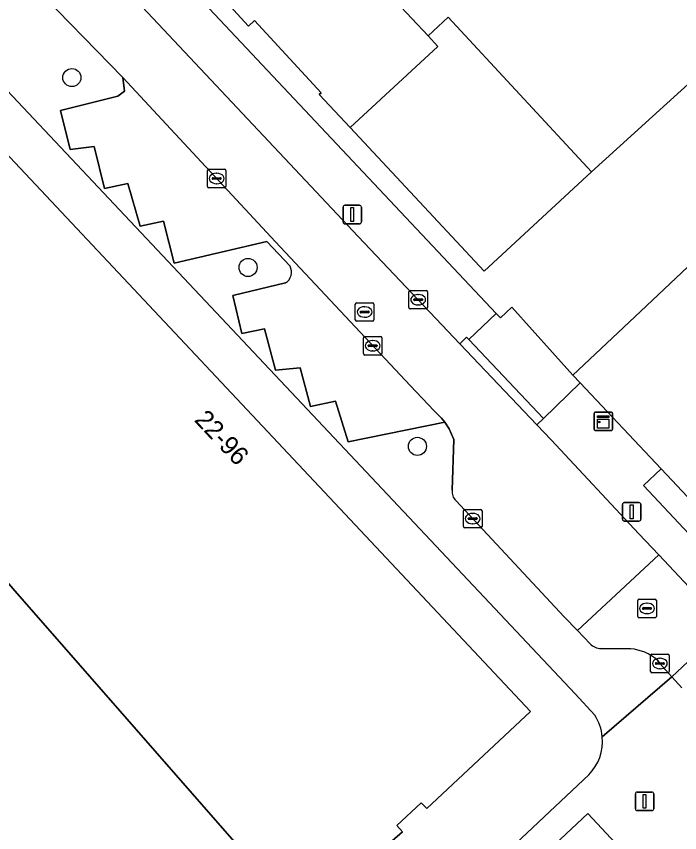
# Model space of a CAD drawing. Extents: x 162344 to 162869, y 381217 to 381818.
# Drawn here: x 162722.83 to 162758.59, y 381421.83 to 381465.85 of the extents above; entities that cross this region are included whole.
import ezdxf

# ---------------------------------------------------------------- set-up
doc = ezdxf.new("R2010")
doc.units = 0
for name, color, linetype in [('IMGEO_Boom', 7, 'Continuous'), ('IMGEO_Erf', 7, 'Continuous'), ('IMGEO_Groenvoorziening', 7, 'Continuous'), ('IMGEO_Kast', 7, 'Continuous'), ('IMGEO_Kolk', 7, 'Continuous'), ('IMGEO_Lichtmast', 7, 'Continuous'), ('IMGEO_Pand', 7, 'Continuous'), ('IMGEO_Pand_nummerreeks', 7, 'Continuous'), ('IMGEO_Pand_overbouw', 7, 'Continuous'), ('IMGEO_Parkeervlak_open', 7, 'Continuous'), ('IMGEO_Rijbaan_lokaal_gesloten', 7, 'Continuous'), ('IMGEO_Rijbaan_lokaal_open', 7, 'Continuous'), ('IMGEO_Rioolput', 7, 'Continuous'), ('IMGEO_Voetpad_open', 7, 'Continuous')]:
    doc.layers.add(name, color=color, linetype=linetype)

msp = doc.modelspace()

# ---------------------------------------------------------------- linework, layer by layer
at = {"layer": 'IMGEO_Boom'}
for centre in [(162725.827, 381462.544), (162735.326, 381452.306), (162744.456, 381442.659)]:
    msp.add_circle(centre, 0.489, dxfattribs=at)
at = {"layer": 'IMGEO_Erf'}
for points in [[(162776.168, 381478.463), (162768.577, 381485.812), (162766.682, 381483.846), (162766.126, 381484.385), (162763.326, 381487.099), (162760.614, 381484.574), (162742.401, 381467.62), (162745.028, 381464.791), (162745.55, 381464.229), (162740.832, 381459.846), (162748.057, 381452.099), (162753.839, 381457.469), (162770.656, 381472.745)], [(162707.761, 381447.96), (162713.091, 381453.729), (162713.48, 381453.373), (162715.221, 381455.005), (162713.929, 381456.387), (162719.413, 381461.511), (162750.55, 381428.359), (162744.956, 381423.125), (162744.66, 381423.433), (162743.338, 381422.213), (162743.645, 381421.881), (162738.243, 381417.16), (162722.757, 381434.865), (162721.886, 381435.861), (162721.396, 381435.328)]]:
    msp.add_lwpolyline(points, close=True, dxfattribs=at)
for points in [[(162754.013, 381428.168), (162752.967, 381429.308), (162720.009, 381464.312)], [(162688.76, 381363.938), (162688.853, 381363.831), (162718.753, 381392.02), (162718.479, 381392.369), (162730.05, 381403.284), (162730.365, 381402.935), (162734.043, 381406.444), (162753.688, 381424.95)]]:
    msp.add_lwpolyline(points, dxfattribs=at)
for centre, radius, start, end in [((162751.844, 381426.758), 2.587, 5.2253, 33.0153), ((162751.847, 381426.762), 2.584, 315.4502, 5.1428)]:
    msp.add_arc(centre, radius, start, end, dxfattribs=at)
at = {"layer": 'IMGEO_Groenvoorziening'}
msp.add_lwpolyline([(162756.875, 381419.391), (162753.639, 381422.863), (162748.623, 381418.154), (162750.4, 381416.271)], dxfattribs=at)
at = {"layer": 'IMGEO_Kast'}
for p, q in [((162753.976, 381443.584), (162753.976, 381444.425)), ((162753.976, 381444.425), (162753.976, 381443.584)), ((162754.051, 381444.509), (162754.892, 381444.509)), ((162754.892, 381444.509), (162754.051, 381444.509)), ((162754.976, 381444.434), (162754.976, 381443.593)), ((162754.976, 381443.593), (162754.976, 381444.434)), ((162754.901, 381443.509), (162754.06, 381443.509)), ((162754.06, 381443.509), (162754.901, 381443.509))]:
    msp.add_line(p, q, dxfattribs=at)
for points in [[(162754.171, 381444.299), (162754.771, 381444.299), (162754.771, 381444.214), (162754.171, 381444.214), (162754.171, 381444.299)], [(162754.171, 381444.124), (162754.771, 381444.124), (162754.771, 381443.635), (162754.171, 381443.635), (162754.171, 381444.124)]]:
    msp.add_lwpolyline(points, dxfattribs=at)
msp.add_circle((162754.255, 381443.973), 0.0377, dxfattribs=at)
for centre, start, end in [((162754.054, 381444.431), 92.4484, 184.2845), ((162754.054, 381444.431), 92.4484, 184.2845), ((162754.898, 381444.431), 2.4484, 94.2845), ((162754.898, 381444.431), 2.4484, 94.2845), ((162754.054, 381443.587), 182.4484, 274.2845), ((162754.054, 381443.587), 182.4484, 274.2845), ((162754.898, 381443.587), 272.4484, 4.2845), ((162754.898, 381443.587), 272.4484, 4.2845)]:
    msp.add_arc(centre, 0.0779, start, end, dxfattribs=at)
at = {"layer": 'IMGEO_Kolk'}
for p, q in [((162733.134, 381456.676), (162733.134, 381457.528)), ((162733.209, 381457.602), (162734.061, 381457.602)), ((162733.622, 381457.382), (162733.647, 381457.382)), ((162734.135, 381457.528), (162734.135, 381456.676)), ((162733.393, 381457.096), (162733.393, 381457.108)), ((162733.831, 381457.059), (162733.433, 381457.059)), ((162733.436, 381457.145), (162733.834, 381457.145)), ((162733.877, 381457.108), (162733.877, 381457.096)), ((162734.061, 381456.602), (162733.209, 381456.602)), ((162733.645, 381456.822), (162733.62, 381456.822)), ((162743.995, 381450.141), (162743.995, 381450.993)), ((162744.07, 381451.067), (162744.922, 381451.067)), ((162744.483, 381450.847), (162744.508, 381450.847)), ((162744.996, 381450.993), (162744.996, 381450.141)), ((162744.254, 381450.561), (162744.254, 381450.573)), ((162744.692, 381450.524), (162744.294, 381450.524)), ((162744.297, 381450.61), (162744.695, 381450.61)), ((162744.738, 381450.573), (162744.738, 381450.561)), ((162744.922, 381450.067), (162744.07, 381450.067)), ((162744.506, 381450.287), (162744.481, 381450.287)), ((162741.617, 381448.584), (162742.469, 381448.584)), ((162741.542, 381447.658), (162741.542, 381448.51)), ((162741.844, 381448.127), (162742.242, 381448.127)), ((162742.03, 381448.364), (162742.055, 381448.364)), ((162742.543, 381448.51), (162742.543, 381447.658)), ((162741.801, 381448.078), (162741.801, 381448.09)), ((162742.239, 381448.041), (162741.841, 381448.041)), ((162742.053, 381447.804), (162742.028, 381447.804)), ((162742.285, 381448.09), (162742.285, 381448.078)), ((162742.469, 381447.584), (162741.617, 381447.584)), ((162746.936, 381438.336), (162746.936, 381439.188)), ((162747.011, 381439.262), (162747.863, 381439.262)), ((162747.424, 381439.042), (162747.449, 381439.042)), ((162747.937, 381439.188), (162747.937, 381438.336)), ((162747.195, 381438.756), (162747.195, 381438.768)), ((162747.633, 381438.719), (162747.235, 381438.719)), ((162747.238, 381438.805), (162747.636, 381438.805)), ((162747.447, 381438.482), (162747.422, 381438.482)), ((162747.679, 381438.768), (162747.679, 381438.756)), ((162747.863, 381438.262), (162747.011, 381438.262)), ((162757.099, 381431.45), (162757.951, 381431.45)), ((162757.024, 381430.524), (162757.024, 381431.376)), ((162757.283, 381430.944), (162757.283, 381430.956)), ((162757.326, 381430.993), (162757.724, 381430.993)), ((162757.512, 381431.23), (162757.537, 381431.23)), ((162757.767, 381430.956), (162757.767, 381430.944)), ((162758.025, 381431.376), (162758.025, 381430.524)), ((162757.721, 381430.907), (162757.323, 381430.907)), ((162757.535, 381430.67), (162757.51, 381430.67)), ((162757.951, 381430.45), (162757.099, 381430.45))]:
    msp.add_line(p, q, dxfattribs=at)
for points in [[(162733.134, 381456.676), (162733.134, 381457.528)], [(162733.209, 381457.602), (162734.061, 381457.602)], [(162734.135, 381457.528), (162734.135, 381456.676)], [(162734.061, 381456.602), (162733.209, 381456.602)], [(162743.995, 381450.141), (162743.995, 381450.993)], [(162744.07, 381451.067), (162744.922, 381451.067)], [(162744.996, 381450.993), (162744.996, 381450.141)], [(162744.922, 381450.067), (162744.07, 381450.067)], [(162741.617, 381448.584), (162742.469, 381448.584)], [(162741.542, 381447.658), (162741.542, 381448.51)], [(162742.543, 381448.51), (162742.543, 381447.658)], [(162742.469, 381447.584), (162741.617, 381447.584)], [(162746.936, 381438.336), (162746.936, 381439.188)], [(162747.011, 381439.262), (162747.863, 381439.262)], [(162747.937, 381439.188), (162747.937, 381438.336)], [(162747.863, 381438.262), (162747.011, 381438.262)], [(162757.099, 381431.45), (162757.951, 381431.45)], [(162757.024, 381430.524), (162757.024, 381431.376)], [(162758.025, 381431.376), (162758.025, 381430.524)], [(162757.951, 381430.45), (162757.099, 381430.45)]]:
    msp.add_lwpolyline(points, dxfattribs=at)
for centre, radius, start, end in [((162733.211, 381457.526), 0.0765, 91.552, 178.448), ((162733.211, 381457.526), 0.0765, 91.552, 178.448), ((162734.059, 381457.526), 0.0765, 1.552, 88.448), ((162734.059, 381457.526), 0.0765, 1.552, 88.448), ((162733.433, 381457.105), 0.0403, 85.8775, 175.7526), ((162733.43, 381457.095), 0.0366, 178.938, 274.7102), ((162733.834, 381457.102), 0.043, 264.8664, 352.4533), ((162733.838, 381457.107), 0.0386, 1.7309, 96.639), ((162733.211, 381456.678), 0.0765, 181.552, 268.448), ((162733.211, 381456.678), 0.0765, 181.552, 268.448), ((162734.059, 381456.678), 0.0765, 271.552, 358.448), ((162734.059, 381456.678), 0.0765, 271.552, 358.448), ((162744.072, 381450.991), 0.0765, 91.552, 178.448), ((162744.072, 381450.991), 0.0765, 91.552, 178.448), ((162744.92, 381450.991), 0.0765, 1.552, 88.448), ((162744.92, 381450.991), 0.0765, 1.552, 88.448), ((162744.294, 381450.57), 0.0403, 85.8775, 175.7526), ((162744.291, 381450.56), 0.0366, 178.938, 274.7102), ((162744.695, 381450.567), 0.043, 264.8664, 352.4533), ((162744.699, 381450.572), 0.0386, 1.7309, 96.639), ((162744.072, 381450.143), 0.0765, 181.552, 268.448), ((162744.072, 381450.143), 0.0765, 181.552, 268.448), ((162744.92, 381450.143), 0.0765, 271.552, 358.448), ((162744.92, 381450.143), 0.0765, 271.552, 358.448), ((162741.619, 381448.508), 0.0765, 91.552, 178.448), ((162741.619, 381448.508), 0.0765, 91.552, 178.448), ((162742.467, 381448.508), 0.0765, 1.552, 88.448), ((162742.467, 381448.508), 0.0765, 1.552, 88.448), ((162741.841, 381448.087), 0.0403, 85.8775, 175.7526), ((162742.246, 381448.089), 0.0386, 1.7309, 96.639), ((162741.838, 381448.077), 0.0366, 178.938, 274.7102), ((162742.242, 381448.084), 0.043, 264.8664, 352.4533), ((162741.619, 381447.66), 0.0765, 181.552, 268.448), ((162741.619, 381447.66), 0.0765, 181.552, 268.448), ((162742.467, 381447.66), 0.0765, 271.552, 358.448), ((162742.467, 381447.66), 0.0765, 271.552, 358.448), ((162747.013, 381439.186), 0.0765, 91.552, 178.448), ((162747.013, 381439.186), 0.0765, 91.552, 178.448), ((162747.861, 381439.186), 0.0765, 1.552, 88.448), ((162747.861, 381439.186), 0.0765, 1.552, 88.448), ((162747.235, 381438.765), 0.0403, 85.8775, 175.7526), ((162747.232, 381438.755), 0.0366, 178.938, 274.7102), ((162747.636, 381438.762), 0.043, 264.8664, 352.4533), ((162747.64, 381438.767), 0.0386, 1.7309, 96.639), ((162747.013, 381438.338), 0.0765, 181.552, 268.448), ((162747.013, 381438.338), 0.0765, 181.552, 268.448), ((162747.861, 381438.338), 0.0765, 271.552, 358.448), ((162747.861, 381438.338), 0.0765, 271.552, 358.448), ((162757.101, 381431.374), 0.0765, 91.552, 178.448), ((162757.101, 381431.374), 0.0765, 91.552, 178.448), ((162757.949, 381431.374), 0.0765, 1.552, 88.448), ((162757.949, 381431.374), 0.0765, 1.552, 88.448), ((162757.323, 381430.953), 0.0403, 85.8775, 175.7526), ((162757.728, 381430.955), 0.0386, 1.7309, 96.639), ((162757.101, 381430.526), 0.0765, 181.552, 268.448), ((162757.101, 381430.526), 0.0765, 181.552, 268.448), ((162757.32, 381430.943), 0.0366, 178.938, 274.7102), ((162757.724, 381430.95), 0.043, 264.8664, 352.4533), ((162757.949, 381430.526), 0.0765, 271.552, 358.448), ((162757.949, 381430.526), 0.0765, 271.552, 358.448)]:
    msp.add_arc(centre, radius, start, end, dxfattribs=at)
for centre, major_axis, ratio, start_param, end_param in [((162733.621, 381457.102), (-0.387, 0.002), 0.722429, 4.712389, 7.853982), ((162733.646, 381457.102), (-0.39, 0.002), 0.717154, 1.570796, 4.712389), ((162744.482, 381450.567), (-0.387, 0.002), 0.722429, 4.712389, 7.853982), ((162744.507, 381450.567), (-0.39, 0.002), 0.717154, 1.570796, 4.712389), ((162742.029, 381448.084), (-0.387, 0.002), 0.722429, 4.712389, 7.853982), ((162742.054, 381448.084), (-0.39, 0.002), 0.717154, 1.570796, 4.712389), ((162747.423, 381438.762), (-0.387, 0.002), 0.722429, 4.712389, 7.853982), ((162747.448, 381438.762), (-0.39, 0.002), 0.717154, 1.570796, 4.712389), ((162757.511, 381430.95), (-0.387, 0.002), 0.722429, 4.712389, 7.853982), ((162757.536, 381430.95), (-0.39, 0.002), 0.717154, 1.570796, 4.712389)]:
    msp.add_ellipse(centre, major_axis=major_axis, ratio=ratio, start_param=start_param, end_param=end_param, dxfattribs=at)
at = {"layer": 'IMGEO_Lichtmast'}
for p, q in [((162740.543, 381455.657), (162741.333, 381455.657)), ((162741.333, 381455.657), (162740.543, 381455.657)), ((162740.443, 381454.757), (162740.443, 381455.557)), ((162740.443, 381455.557), (162740.443, 381454.757)), ((162741.433, 381455.557), (162741.433, 381454.757)), ((162741.433, 381454.757), (162741.433, 381455.557)), ((162741.333, 381454.657), (162740.543, 381454.657)), ((162740.543, 381454.657), (162741.333, 381454.657)), ((162755.508, 381438.727), (162755.508, 381439.527)), ((162755.508, 381439.527), (162755.508, 381438.727)), ((162755.608, 381439.627), (162756.398, 381439.627)), ((162756.398, 381439.627), (162755.608, 381439.627)), ((162756.498, 381439.527), (162756.498, 381438.727)), ((162756.498, 381438.727), (162756.498, 381439.527)), ((162756.398, 381438.627), (162755.608, 381438.627)), ((162755.608, 381438.627), (162756.398, 381438.627)), ((162756.205, 381423.118), (162756.205, 381423.918)), ((162756.205, 381423.918), (162756.205, 381423.118)), ((162756.305, 381424.018), (162757.095, 381424.018)), ((162757.095, 381424.018), (162756.305, 381424.018)), ((162757.195, 381423.918), (162757.195, 381423.118)), ((162757.195, 381423.118), (162757.195, 381423.918)), ((162757.095, 381423.018), (162756.305, 381423.018)), ((162756.305, 381423.018), (162757.095, 381423.018))]:
    msp.add_line(p, q, dxfattribs=at)
for points in [[(162740.863, 381455.532), (162741.013, 381455.532), (162741.013, 381454.782), (162740.863, 381454.782), (162740.863, 381455.532)], [(162755.928, 381439.502), (162756.078, 381439.502), (162756.078, 381438.752), (162755.928, 381438.752), (162755.928, 381439.502)], [(162756.625, 381423.893), (162756.775, 381423.893), (162756.775, 381423.143), (162756.625, 381423.143), (162756.625, 381423.893)]]:
    msp.add_lwpolyline(points, dxfattribs=at)
for centre, start, end in [((162740.543, 381455.557), 90, 180), ((162740.543, 381455.557), 90, 180), ((162741.333, 381455.557), 0, 90), ((162741.333, 381455.557), 360, 90), ((162740.543, 381454.757), 180, 270), ((162740.543, 381454.757), 180, 270), ((162741.333, 381454.757), 270, 0), ((162741.333, 381454.757), 270, 0), ((162755.608, 381439.527), 90, 180), ((162755.608, 381439.527), 90, 180), ((162756.398, 381439.527), 0, 90), ((162756.398, 381439.527), 360, 90), ((162755.608, 381438.727), 180, 270), ((162755.608, 381438.727), 180, 270), ((162756.398, 381438.727), 270, 0), ((162756.398, 381438.727), 270, 0), ((162756.305, 381423.918), 90, 180), ((162756.305, 381423.918), 90, 180), ((162757.095, 381423.918), 0, 90), ((162757.095, 381423.918), 360, 90), ((162756.305, 381423.118), 180, 270), ((162756.305, 381423.118), 180, 270), ((162757.095, 381423.118), 270, 0), ((162757.095, 381423.118), 270, 0)]:
    msp.add_arc(centre, 0.1, start, end, dxfattribs=at)
at = {"layer": 'IMGEO_Pand'}
for points in [[(162766.126, 381484.385), (162766.682, 381483.846), (162768.577, 381485.812), (162768.536, 381485.851), (162758.304, 381495.766), (162752.699, 381489.967), (162754.084, 381488.603), (162751.474, 381486.208), (162750.603, 381487.146), (162742.067, 381479.233), (162741.819, 381479.502), (162731.299, 381469.745), (162735.357, 381465.316), (162735.681, 381465.613), (162739.259, 381461.73), (162739.157, 381461.634), (162740.832, 381459.846), (162745.55, 381464.229), (162745.028, 381464.791), (162742.401, 381467.62), (162760.614, 381484.574), (162763.326, 381487.099)], [(162752.835, 381446.506), (162753.232, 381446.083), (162757.597, 381441.444), (162762.133, 381436.621), (162793.032, 381465.683), (162788.482, 381470.52), (162783.734, 381475.568), (162780.092, 381472.143), (162777.709, 381469.901), (162778.4, 381469.165), (162775.312, 381466.261), (162774.596, 381467.023), (162762.149, 381455.316), (162762.834, 381454.587), (162759.69, 381451.63), (162759.03, 381452.332), (162756.477, 381449.931)], [(162713.929, 381456.387), (162715.221, 381455.005), (162713.48, 381453.373), (162713.091, 381453.729), (162707.761, 381447.96), (162721.396, 381435.328), (162721.886, 381435.861), (162722.757, 381434.865), (162738.243, 381417.16), (162743.645, 381421.881), (162743.338, 381422.213), (162744.66, 381423.433), (162744.956, 381423.125), (162750.55, 381428.359), (162719.413, 381461.511)]]:
    msp.add_lwpolyline(points, close=True, dxfattribs=at)
at = {"layer": 'IMGEO_Pand_overbouw'}
msp.add_lwpolyline([(162746.112, 381465.798), (162745.028, 381464.791), (162745.55, 381464.229), (162740.832, 381459.846), (162748.057, 381452.099), (162753.839, 381457.469)], close=True, dxfattribs=at)
at = {"layer": 'IMGEO_Parkeervlak_open'}
msp.add_lwpolyline([(162737.337, 381451.473), (162734.498, 381450.795), (162734.993, 381448.741), (162736.21, 381448.99), (162736.808, 381446.772), (162738.127, 381446.895), (162738.686, 381444.816), (162740.043, 381445.104), (162740.729, 381442.9), (162745.941, 381443.968), (162745.755, 381444.185), (162745.358, 381444.567), (162744.056, 381445.934), (162736.812, 381453.682), (162728.576, 381462.553), (162728.666, 381461.803), (162728.3, 381461.547), (162725.207, 381460.778), (162725.728, 381458.662), (162727.034, 381458.822), (162727.594, 381456.566), (162728.837, 381456.828), (162729.511, 381454.534), (162730.766, 381454.796), (162731.339, 381452.54), (162736.333, 381453.714), (162737.586, 381452.376)], dxfattribs=at)
msp.add_arc((162736.998, 381452.052), 0.671, 300.3536, 28.8143, dxfattribs=at)
at = {"layer": 'IMGEO_Rijbaan_lokaal_gesloten'}
for points in [[(162751.665, 381443.002), (162750.893, 381443.816), (162746.741, 381448.196), (162741.261, 381453.977), (162726.224, 381469.983), (162725.57, 381470.679), (162722.909, 381468.374), (162723.627, 381467.636), (162728.576, 381462.553), (162736.812, 381453.682), (162744.056, 381445.934), (162745.358, 381444.567), (162745.755, 381444.185), (162745.941, 381443.968), (162746.172, 381443.603), (162746.409, 381443.032), (162746.335, 381440.302)], [(162746.532, 381439.731), (162752.372, 381433.475), (162753.083, 381432.727), (162757.473, 381436.804), (162756.391, 381437.951), (162751.665, 381443.002)]]:
    msp.add_lwpolyline(points, dxfattribs=at)
msp.add_arc((162746.951, 381440.195), 0.625, 170.1446, 227.9252, dxfattribs=at)
at = {"layer": 'IMGEO_Rijbaan_lokaal_open'}
for points in [[(162757.473, 381436.804), (162753.083, 381432.727), (162753.768, 381432.007)], [(162757.39, 381431.122), (162757.525, 381430.95), (162758.176, 381430.227), (162761.099, 381432.973), (162760.457, 381433.637), (162757.473, 381436.804)], [(162761.657, 381432.397), (162761.099, 381432.973), (162758.176, 381430.227), (162758.705, 381429.64)], [(162754.359, 381431.752), (162755.949, 381431.738)]]:
    msp.add_lwpolyline(points, dxfattribs=at)
for centre, radius, start, end in [((162754.388, 381432.631), 0.88, 225.2051, 268.1172), ((162755.801, 381429.398), 2.344, 47.3292, 86.3792)]:
    msp.add_arc(centre, radius, start, end, dxfattribs=at)
at = {"layer": 'IMGEO_Rioolput'}
for p, q in [((162741.107, 381449.478), (162741.107, 381450.33)), ((162741.182, 381450.404), (162742.034, 381450.404)), ((162742.108, 381450.33), (162742.108, 381449.478)), ((162741.366, 381449.898), (162741.366, 381449.91)), ((162741.409, 381449.947), (162741.807, 381449.947)), ((162741.595, 381450.184), (162741.62, 381450.184)), ((162741.85, 381449.91), (162741.85, 381449.898)), ((162741.804, 381449.861), (162741.406, 381449.861)), ((162741.618, 381449.624), (162741.593, 381449.624)), ((162742.034, 381449.404), (162741.182, 381449.404)), ((162756.335, 381433.493), (162756.335, 381434.345)), ((162756.41, 381434.419), (162757.262, 381434.419)), ((162756.823, 381434.199), (162756.848, 381434.199)), ((162757.336, 381434.345), (162757.336, 381433.493)), ((162756.594, 381433.913), (162756.594, 381433.925)), ((162757.032, 381433.876), (162756.634, 381433.876)), ((162756.637, 381433.962), (162757.035, 381433.962)), ((162756.846, 381433.639), (162756.821, 381433.639)), ((162757.078, 381433.925), (162757.078, 381433.913)), ((162757.262, 381433.419), (162756.41, 381433.419))]:
    msp.add_line(p, q, dxfattribs=at)
for points in [[(162741.107, 381449.478), (162741.107, 381450.33)], [(162741.182, 381450.404), (162742.034, 381450.404)], [(162742.108, 381450.33), (162742.108, 381449.478)], [(162742.034, 381449.404), (162741.182, 381449.404)], [(162756.335, 381433.493), (162756.335, 381434.345)], [(162756.41, 381434.419), (162757.262, 381434.419)], [(162757.336, 381434.345), (162757.336, 381433.493)], [(162757.262, 381433.419), (162756.41, 381433.419)]]:
    msp.add_lwpolyline(points, dxfattribs=at)
for centre, radius, start, end in [((162741.184, 381450.328), 0.0765, 91.552, 178.448), ((162741.184, 381450.328), 0.0765, 91.552, 178.448), ((162742.032, 381450.328), 0.0765, 1.552, 88.448), ((162742.032, 381450.328), 0.0765, 1.552, 88.448), ((162741.406, 381449.907), 0.0403, 85.8775, 175.7526), ((162741.403, 381449.897), 0.0366, 178.938, 274.7102), ((162741.807, 381449.904), 0.043, 264.8664, 352.4533), ((162741.811, 381449.909), 0.0386, 1.7309, 96.639), ((162741.184, 381449.48), 0.0765, 181.552, 268.448), ((162741.184, 381449.48), 0.0765, 181.552, 268.448), ((162742.032, 381449.48), 0.0765, 271.552, 358.448), ((162742.032, 381449.48), 0.0765, 271.552, 358.448), ((162756.412, 381434.343), 0.0765, 91.552, 178.448), ((162756.412, 381434.343), 0.0765, 91.552, 178.448), ((162757.26, 381434.343), 0.0765, 1.552, 88.448), ((162757.26, 381434.343), 0.0765, 1.552, 88.448), ((162756.634, 381433.922), 0.0403, 85.8775, 175.7526), ((162756.631, 381433.912), 0.0366, 178.938, 274.7102), ((162757.035, 381433.919), 0.043, 264.8664, 352.4533), ((162757.039, 381433.924), 0.0386, 1.7309, 96.639), ((162756.412, 381433.495), 0.0765, 181.552, 268.448), ((162756.412, 381433.495), 0.0765, 181.552, 268.448), ((162757.26, 381433.495), 0.0765, 271.552, 358.448), ((162757.26, 381433.495), 0.0765, 271.552, 358.448)]:
    msp.add_arc(centre, radius, start, end, dxfattribs=at)
for centre, major_axis, ratio, start_param, end_param in [((162741.594, 381449.904), (-0.387, 0.002), 0.722429, 4.712389, 7.853982), ((162741.619, 381449.904), (-0.39, 0.002), 0.717154, 1.570796, 4.712389), ((162756.822, 381433.919), (-0.387, 0.002), 0.722429, 4.712389, 7.853982), ((162756.847, 381433.919), (-0.39, 0.002), 0.717154, 1.570796, 4.712389)]:
    msp.add_ellipse(centre, major_axis=major_axis, ratio=ratio, start_param=start_param, end_param=end_param, dxfattribs=at)
at = {"layer": 'IMGEO_Voetpad_open'}
for points in [[(162693.224, 381503.598), (162694.183, 381504.531), (162698.437, 381500), (162716.08, 381481.206), (162716.52, 381480.737), (162716.838, 381480.398), (162725.57, 381470.679), (162726.224, 381469.983), (162741.261, 381453.977), (162746.741, 381448.196), (162747.105, 381448.538), (162747.223, 381448.414), (162748.704, 381449.828), (162728.071, 381471.775), (162727.352, 381472.54), (162718.237, 381482.347), (162714.352, 381486.527), (162670.77, 381532.927)], [(162752.83, 381503.069), (162756.143, 381499.572), (162756.429, 381499.537), (162757.278, 381498.665), (162733.851, 381476.965), (162733.188, 381477.672), (162733.194, 381477.966), (162729.869, 381481.474), (162728.765, 381480.422), (162727.115, 381482.137), (162723.562, 381478.758), (162728.361, 381473.453), (162727.352, 381472.54), (162728.071, 381471.775), (162748.704, 381449.828), (162748.933, 381449.585), (162749.553, 381450.159), (162752.835, 381446.506), (162756.477, 381449.931), (162759.03, 381452.332)], [(162737.586, 381452.376), (162736.333, 381453.714), (162731.339, 381452.54), (162730.766, 381454.796), (162729.511, 381454.534), (162728.837, 381456.828), (162727.594, 381456.566), (162727.034, 381458.822), (162725.728, 381458.662), (162725.207, 381460.778), (162728.3, 381461.547), (162728.666, 381461.803), (162728.576, 381462.553), (162723.627, 381467.636), (162722.465, 381466.568), (162720.009, 381464.312), (162752.967, 381429.308), (162754.013, 381428.168)], [(162746.409, 381443.032), (162746.172, 381443.603), (162745.941, 381443.968), (162740.729, 381442.9), (162740.043, 381445.104), (162738.686, 381444.816), (162738.127, 381446.895), (162736.808, 381446.772), (162736.21, 381448.99), (162734.993, 381448.741), (162734.498, 381450.795), (162737.337, 381451.473)], [(162746.335, 381440.302), (162746.409, 381443.032)], [(162753.768, 381432.007), (162753.083, 381432.727), (162752.372, 381433.475), (162746.532, 381439.731)], [(162755.949, 381431.738), (162754.359, 381431.752)], [(162754.42, 381426.994), (162758.176, 381430.227), (162757.525, 381430.95), (162757.39, 381431.122)], [(162758.705, 381429.64), (162758.176, 381430.227), (162754.42, 381426.994)], [(162753.688, 381424.95), (162734.043, 381406.444), (162730.365, 381402.935), (162730.05, 381403.284), (162718.479, 381392.369), (162718.753, 381392.02), (162688.853, 381363.831), (162685.116, 381360.607), (162681.529, 381357.23), (162682.924, 381355.768)], [(162750.4, 381416.271), (162748.623, 381418.154), (162753.639, 381422.863), (162756.875, 381419.391), (162758.592, 381421.029)]]:
    msp.add_lwpolyline(points, dxfattribs=at)
for points in [[(162753.839, 381457.469), (162748.057, 381452.099), (162740.832, 381459.846), (162739.157, 381461.634), (162739.259, 381461.73), (162735.681, 381465.613), (162735.357, 381465.316), (162731.299, 381469.745), (162741.819, 381479.502), (162742.067, 381479.233), (162750.603, 381487.146), (162751.474, 381486.208), (162754.084, 381488.603), (162752.699, 381489.967), (162758.304, 381495.766), (162768.536, 381485.851), (162768.577, 381485.812), (162776.168, 381478.463), (162770.656, 381472.745)], [(162789.445, 381471.426), (162788.482, 381470.52), (162793.032, 381465.683), (162762.133, 381436.621), (162757.597, 381441.444), (162756.636, 381440.54), (162761.266, 381435.618), (162762.117, 381434.713), (162794.926, 381465.598), (162794.012, 381466.57)], [(162752.835, 381446.506), (162749.553, 381450.159), (162748.933, 381449.585), (162748.704, 381449.828), (162747.223, 381448.414), (162751.252, 381444.164), (162753.232, 381446.083)], [(162747.223, 381448.414), (162747.105, 381448.538), (162746.741, 381448.196), (162750.893, 381443.816), (162751.252, 381444.164)], [(162753.232, 381446.083), (162751.252, 381444.164), (162750.893, 381443.816), (162751.665, 381443.002), (162756.391, 381437.951), (162757.473, 381436.804), (162760.457, 381433.637), (162761.099, 381432.973), (162762.117, 381434.713), (162761.266, 381435.618), (162756.636, 381440.54), (162757.597, 381441.444)]]:
    msp.add_lwpolyline(points, close=True, dxfattribs=at)
for centre, radius, start, end in [((162736.998, 381452.052), 0.671, 300.3536, 28.8143), ((162746.951, 381440.195), 0.625, 170.1446, 227.9252), ((162754.388, 381432.631), 0.88, 225.2051, 268.1172), ((162755.801, 381429.398), 2.344, 47.3292, 86.3792), ((162751.844, 381426.758), 2.587, 5.2253, 33.0153), ((162751.847, 381426.762), 2.584, 315.4502, 5.1428)]:
    msp.add_arc(centre, radius, start, end, dxfattribs=at)

# ---------------------------------------------------------------- texts
at = {"layer": 'IMGEO_Pand_nummerreeks'}
msp.add_text('22-96', height=1, rotation=313.2065, dxfattribs=at).set_placement((162732.385, 381444.047))

doc.saveas('drawing.dxf')
